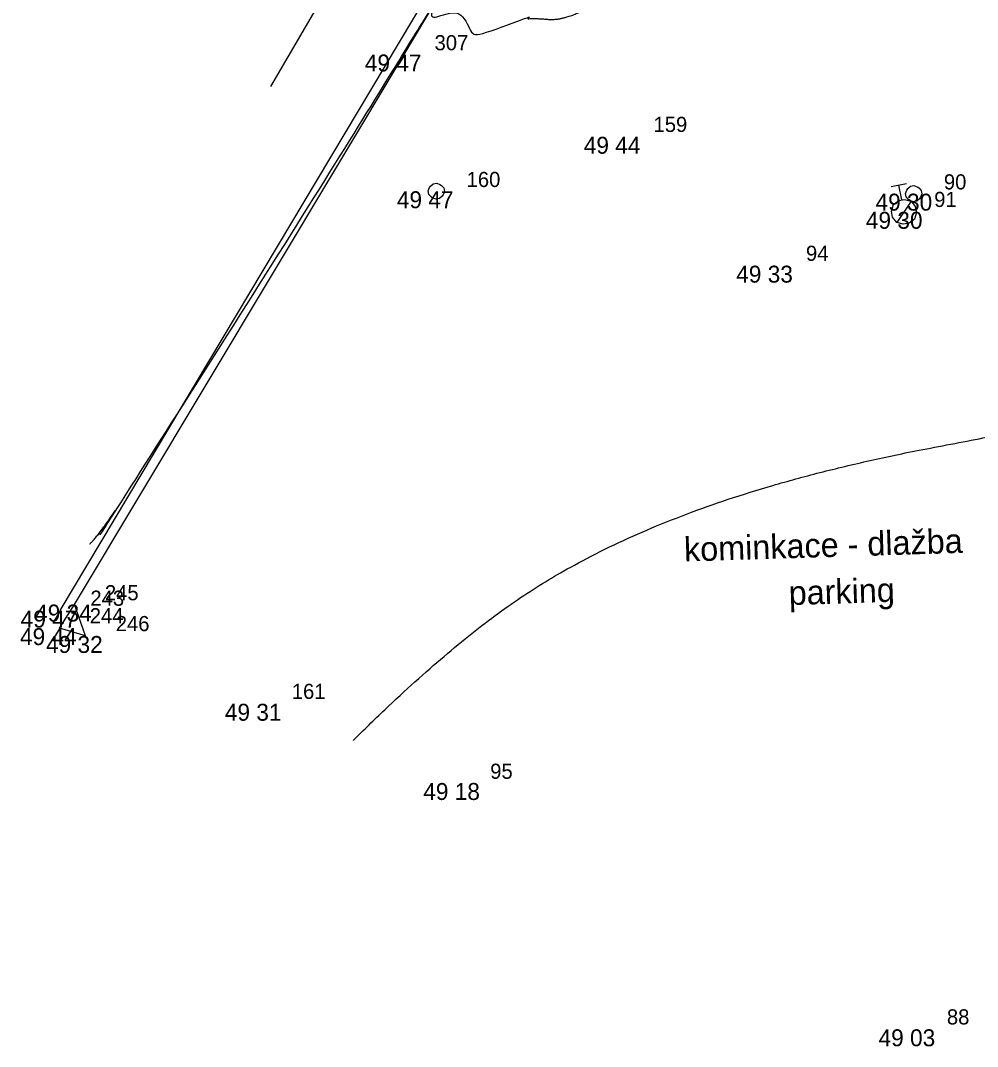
# Model space of a CAD drawing. Extents: x -704017 to -701500, y -1008977 to -1008450.
# Drawn here: x -701775.11 to -701759.29, y -1008967.52 to -1008950.57 of the extents above; entities that cross this region are included whole.
import ezdxf

# ---------------------------------------------------------------- set-up
doc = ezdxf.new("R2010")
doc.units = 0
for name, color, linetype in [('Z_body', 7, 'Continuous'), ('Z_body_cisla', 7, 'Continuous'), ('Z_body_vysky', 7, 'Continuous'), ('Z_budovy', 7, 'Continuous'), ('Z_komunikace', 7, 'Continuous'), ('Z_obruby', 7, 'Continuous'), ('Z_popis', 7, 'Continuous'), ('Z_site_znaky_plynovod', 7, 'Continuous'), ('Z_site_znaky_vodovod', 7, 'Continuous'), ('Z_teren_hrany_paty', 7, 'Continuous'), ('Z_vrstevnice_vedlejsi', 7, 'Continuous')]:
    doc.layers.add(name, color=color, linetype=linetype)

# ---------------------------------------------------------------- blocks, each defined once
blk = doc.blocks.new('POINT_DISPLAY')
blk.add_line((0, 0), (0, 0))
blk = doc.blocks.new('Z614')
for p, q in [((-0.13, 0.03), (-0.1, 0.08)), ((-0.13, -0.03), (-0.13, 0.03)), ((-0.1, 0.08), (-0.08, 0.1)), ((-0.08, 0.1), (-0.03, 0.13)), ((-0.03, 0.13), (0.03, 0.13)), ((0.03, 0.13), (0.08, 0.1)), ((0.08, 0.1), (0.1, 0.08)), ((0.1, 0.08), (0.13, 0.03)), ((0.13, 0.03), (0.13, -0.03)), ((-0.1, -0.08), (-0.13, -0.03)), ((-0.08, -0.1), (-0.1, -0.08)), ((-0.03, -0.13), (-0.08, -0.1)), ((0.03, -0.13), (-0.03, -0.13)), ((0.08, -0.1), (0.03, -0.13)), ((0.1, -0.08), (0.08, -0.1)), ((0.13, -0.03), (0.1, -0.08))]:
    blk.add_line(p, q)
blk = doc.blocks.new('Z18')
for p, q in [((-0.13, 0.45), (0.13, 0.45)), ((0, 0.2), (0, 0.45)), ((-0.15, 0.15), (-0.05, 0.2)), ((-0.05, 0.2), (0.05, 0.2)), ((0.05, 0.2), (0.15, 0.15)), ((-0.2, 0.05), (-0.15, 0.15)), ((-0.2, -0.05), (-0.2, 0.05)), ((0.15, 0.15), (-0.15, -0.15)), ((0.15, 0.15), (0.2, 0.05)), ((0.2, 0.05), (0.2, -0.05)), ((-0.15, -0.15), (-0.2, -0.05)), ((-0.05, -0.2), (-0.15, -0.15)), ((0.15, -0.15), (0.05, -0.2)), ((0.2, -0.05), (0.15, -0.15)), ((0.05, -0.2), (-0.05, -0.2))]:
    blk.add_line(p, q)

msp = doc.modelspace()

# ---------------------------------------------------------------- linework, layer by layer
at = {"layer": 'Z_budovy'}
msp.add_line((-701769.41, -1008948.96), (-701770.98, -1008951.66), dxfattribs=at)
at = {"layer": 'Z_komunikace'}
for p, q in [((-701768.77, -1008951.13), (-701768.02, -1008949.87)), ((-701774.22, -1008960.22), (-701768.77, -1008951.13)), ((-701774.47, -1008960.61), (-701774.22, -1008960.22))]:
    msp.add_line(p, q, dxfattribs=at)
at = {"layer": 'Z_obruby'}
msp.add_line((-701774.46, -1008960.32), (-701767.67, -1008948.95), dxfattribs=at)
at = {"layer": 'Z_teren_hrany_paty'}
for q in [(-701774.22, -1008960.22), (-701774.47, -1008960.61)]:
    msp.add_line((-701774.04, -1008960.74), q, dxfattribs=at)
at = {"layer": 'Z_vrstevnice_vedlejsi'}
for points in [[(-701773.971, -1008959.221), (-701773.611, -1008958.899), (-701768.633, -1008950.858), (-701768.32, -1008950.374), (-701768.26, -1008950.536), (-701767.757, -1008950.395), (-701767.625, -1008950.96), (-701767.096, -1008950.484), (-701765.713, -1008950.612), (-701763.054, -1008947.869), (-701762.897, -1008947.613), (-701762.622, -1008947.644), (-701762.63, -1008947.61), (-701762.506, -1008947.635), (-701760.8, -1008947.99), (-701759.208, -1008948.143), (-701758.947, -1008948.041), (-701758.388, -1008948.143), (-701758.235, -1008948.241), (-701751.691, -1008949.254), (-701747.637, -1008948.233), (-701746.394, -1008948.75), (-701743.001, -1008950.306), (-701742.288, -1008950.624), (-701736.747, -1008953.52), (-701735.858, -1008954.034), (-701735.46, -1008954.08), (-701735.395, -1008953.825), (-701735.333, -1008953.766), (-701735.151, -1008953.611), (-701734.606, -1008953.07), (-701731.409, -1008949.369), (-701730.446, -1008948.79), (-701730.434, -1008950.022), (-701730.433, -1008950.432), (-701730.287, -1008951.52), (-701730.154, -1008952.408), (-701730.018, -1008952.903), (-701729.76, -1008953.885), (-701728.989, -1008953.081), (-701728.637, -1008952.767), (-701728.025, -1008951.97), (-701727.684, -1008951.31), (-701724.593, -1008947.235), (-701724.318, -1008946.646), (-701723.939, -1008946.078), (-701722.809, -1008944.781), (-701722.509, -1008944.53), (-701721.936, -1008943.957), (-701721.659, -1008943.897), (-701721.075, -1008943.473), (-701720.79, -1008943.82), (-701719.4, -1008944.98)], [(-701769.616, -1008962.465), (-701767.944, -1008960.809), (-701765.414, -1008959.18), (-701762.009, -1008957.985), (-701757.483, -1008957.16), (-701757.399, -1008956.341), (-701757.328, -1008956.208), (-701751.702, -1008955.174), (-701750.924, -1008954.743), (-701750.62, -1008954.578), (-701749.783, -1008954.69), (-701746.89, -1008955.5), (-701744.604, -1008956.622), (-701741.739, -1008960.56), (-701741.413, -1008960.996), (-701740.237, -1008961.789), (-701732.973, -1008962.64), (-701730.962, -1008963.191), (-701730.381, -1008962.764), (-701730.41, -1008961.433), (-701730.357, -1008960.553), (-701729.64, -1008957.668), (-701729.265, -1008956.205), (-701729.118, -1008956.064), (-701729.046, -1008956.22), (-701729, -1008956.293), (-701728.475, -1008957.185), (-701727.95, -1008958.04), (-701726.55, -1008958.077), (-701726.127, -1008957.693), (-701725.153, -1008956.248), (-701724.861, -1008955.781), (-701723.601, -1008956.966), (-701723.864, -1008957.693), (-701723.677, -1008957.812)]]:
    msp.add_open_spline(points, degree=2, dxfattribs=at)

# ---------------------------------------------------------------- block references
at = {"layer": 'Z_body'}
for p in [(-701768.77, -1008951.13), (-701765.15, -1008952.49), (-701768.24, -1008953.39), (-701760.35, -1008953.43), (-701760.51, -1008953.73), (-701762.63, -1008954.62), (-701774.22, -1008960.22), (-701774.46, -1008960.32), (-701774.47, -1008960.61), (-701774.04, -1008960.74), (-701771.13, -1008961.86), (-701767.85, -1008963.17), (-701760.3, -1008967.24)]:
    msp.add_blockref('POINT_DISPLAY', p, dxfattribs=at)
at = {"layer": 'Z_site_znaky_plynovod', "rotation": 10.799999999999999}
msp.add_blockref('Z614', (-701768.24, -1008953.39), dxfattribs=at)
at = {"layer": 'Z_site_znaky_vodovod', "rotation": 10.799999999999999}
for name, p in [('Z18', (-701760.51, -1008953.73)), ('Z614', (-701760.35, -1008953.43))]:
    msp.add_blockref(name, p, dxfattribs=at)

# ---------------------------------------------------------------- texts
at = {"layer": 'Z_body_cisla'}
for s, p in [('307', (-701768.27, -1008951.06)), ('159', (-701764.65, -1008952.41)), ('160', (-701767.74, -1008953.32)), ('90', (-701759.85, -1008953.36)), ('91', (-701760.01, -1008953.65)), ('94', (-701762.13, -1008954.54)), ('245', (-701773.72, -1008960.15)), ('243', (-701773.96, -1008960.24)), ('244', (-701773.97, -1008960.53)), ('246', (-701773.54, -1008960.66)), ('161', (-701770.63, -1008961.78)), ('95', (-701767.35, -1008963.1)), ('88', (-701759.8, -1008967.16))]:
    msp.add_text(s, height=0.25, dxfattribs=at).set_placement(p)
at = {"layer": 'Z_body_vysky'}
for s, p in [('49 47', (-701769.423, -1008951.41)), ('49 44', (-701765.803, -1008952.77)), ('49 47', (-701768.893, -1008953.67)), ('49 30', (-701760.98, -1008953.71)), ('49 30', (-701761.14, -1008954.01)), ('49 33', (-701763.283, -1008954.9)), ('49 34', (-701774.873, -1008960.5)), ('49 47', (-701775.113, -1008960.6)), ('49 44', (-701775.123, -1008960.89)), ('49 32', (-701774.693, -1008961.02)), ('49 31', (-701771.737, -1008962.14)), ('49 18', (-701768.457, -1008963.45)), ('49 03', (-701760.93, -1008967.52))]:
    msp.add_text(s, height=0.28, dxfattribs=at).set_placement(p)
at = {"layer": 'Z_popis'}
for s, p in [('kominkace - dlažba', (-701764.14, -1008959.51)), ('parking', (-701762.41, -1008960.23))]:
    msp.add_text(s, height=0.4, rotation=1.8, dxfattribs=at).set_placement(p)

doc.saveas('drawing.dxf')
